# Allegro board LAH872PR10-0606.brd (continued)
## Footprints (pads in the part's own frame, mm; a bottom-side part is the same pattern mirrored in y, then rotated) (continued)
2N7002K_SOT23-3
  oval 1.016x1.524 smd: 1(0,0) 2(0.965,2.083) 3(-0.965,2.083)
2N7002KDW_SOT363-6
  oval 0.356x0.889 smd: 1(0,0) 2(0.65,0) 3(1.3,0) 4(1.3,1.6) 5(0.65,1.6) 6(0,1.6)
2N7002KW_SOT323-3
  oval 0.66x0.864 smd: 1(0,0) 2(0.65,1.85) 3(-0.65,1.85)
5A_Z80_0805_2P
  rect 0.813x1.397 smd: 1(0,0) 2(1.702,0)
5A_Z80_0805_2P-NPM
  rect 0.813x1.397 smd: 1(0,0) 2(1.702,0)
5A_Z150_1210_2P
  rect 0.991x2.997 smd: 1(0,0) 2(2.7,0)
ACES_50224-00401-001_4P
  oval 0.61x1.549 smd: 1(0,0) 2(1,0) 3(2,0) 4(3,0)
  rect 1.194x1.803 smd: 5(4.3,-3.875) 6(-1.3,-3.875)
ACES_50458-00601-001_6P-T
  oval 0.559x1.6 smd: 1(0,0) 2(2,0) 3(4,0) 4(6,0) 5(8,0) 6(10,0)
  rect 1.295x2.057 smd: 7(-3.1,-5.175) 8(13.1,-5.175)
ACES_50458-01001-P01_10P-T
  oval 0.559x1.803 smd: 1(0,0) 2(2,0) 3(4,0) 4(6,0) 5(8,0) 6(10,0) 7(12,0) 8(14,0) 9(16,0) 10(18,0)
  rect 1.295x2.057 smd: 11(-3.1,-5.275) 12(21.1,-5.275)
ACES_50673-0120N-001_12P-T
  oval 0.61x1.499 smd: 1(0,0) 3(-1,0) 5(-2,0) 7(-3,0) 9(-4,0) 11(-5,0) 13(-6,0) 15(-7,0) 17(-8,0) 19(-9,0) 21(-10,0) 23(-11,0)
  oval 0.61x1.194 smd: 2(0,2.85) 4(-1,2.85) 6(-2,2.85) 8(-3,2.85) 10(-4,2.85) 12(-5,2.85) 14(-6,2.85) 16(-7,2.85) 18(-8,2.85) 20(-9,2.85) 22(-10,2.85) 24(-11,2.85)
  rect 1.702x2.311 smd: 25(-13.25,1.425) 26(2.25,1.425)
ACES_51522-00801-001_8P
  oval 0.305x1.295 smd: 1(0,0) 2(0.5,0) 3(1,0) 4(1.5,0) 5(2,0) 6(2.5,0) 7(3,0) 8(3.5,0)
  rect 2.489x1.905 smd: 9(5.65,-3.3) 10(-2.15,-3.3)
ACES_51524-0080N-001_8P
  oval 0.61x1.295 smd: 1(0,0) 2(1,0) 3(2,0) 4(3,0) 5(4,0) 6(5,0) 7(6,0) 8(7,0)
  rect 2.489x2.21 smd: 9(10,-3.05) 10(-3,-3.05)
ACES_51524-0160N-001_16P
  oval 0.61x1.295 smd: 1(0,0) 2(1,0) 3(2,0) 4(3,0) 5(4,0) 6(5,0) 7(6,0) 8(7,0) 9(8,0) 10(9,0) 11(10,0) 12(11,0) 13(12,0) 14(13,0) 15(14,0) 16(15,0)
  rect 2.159x2.21 smd: 17(-2.825,-3.05) 18(17.825,-3.05)
ACES_51540-04001-P01_40P
  oval 0.305x1.092 smd: 1(0,0) 2(0.5,0) 3(1,0) 4(1.5,0) 5(2,0) 6(2.5,0) 7(3,0) 8(3.5,0) 9(4,0) 10(4.5,0) 11(5,0) 12(5.5,0) 13(6,0) 14(6.5,0) 15(7,0) 16(7.5,0) 17(8,0) 18(8.5,0) 19(9,0) 20(9.5,0) 21(10,0) 22(10.5,0) 23(11,0) 24(11.5,0) 25(12,0) 26(12.5,0) 27(13,0) 28(13.5,0) 29(14,0) 30(14.5,0) 31(15,0) 32(15.5,0) 33(16,0) 34(16.5,0) 35(17,0) 36(17.5,0) 37(18,0) 38(18.5,0) 39(19,0) 40(19.5,0)
  rect 0.787x2.489 smd: 41(21.2,-3.6) 42(-1.7,-3.6)
ACES_51575-00401-001_4P
  oval 0.406x0.838 smd: 1(0,0) 2(1,0) 3(2,0) 4(3,0)
  rect 0.787x2.007 smd: 5(-2.2,-3.175) 6(5.2,-3.175)
ACES_51625-01201-001_12P
  oval 0.305x1.092 smd: 1(0,0) 2(0.5,0) 3(1,0) 4(1.5,0) 5(2,0) 6(2.5,0) 7(3,0) 8(3.5,0) 9(4,0) 10(4.5,0) 11(5,0) 12(5.5,0)
  rect 0.991x2.489 smd: 13(-1.8,-3.6) 14(7.3,-3.6)
ACON_HMRF6-AK120C_19P-T
  round 0.813 hole 0.559: 1(0,0) 2(0.5,1.55) 3(1,0) 4(1.5,1.55) 5(2,0) 6(2.5,1.55) 7(3,0) 8(3.5,1.55) 9(4,0) 10(4.5,1.55) 11(5,0) 12(5.5,1.55) 13(6,0) 14(6.5,1.55) 15(7,0) 16(7.5,1.55) 17(8,0) 18(8.5,1.55) 19(9,0)
  oval 1.499x2.21 hole 0.889x1.6: 20(11.75,1.7) 21(13.65,-7.75) 22(-4.65,-6.5) 23(-2.75,1.7)
ACON_TARAN-9R1391_9P
  round 0.991 hole 0.711: 1(0,0) 2(-2.5,0) 3(-4.5,0) 4(-7,0) 5(-7.5,-1.5) 6(-5.5,-1.5) 7(-3.5,-1.5) 8(-1.5,-1.5) 9(0.5,-1.5)
  oval 1.397x3.2 hole 0.787x2.591: 10(-11.35,-2.38) 12(4.35,-2.38)
  oval 1.397x2.388 hole 0.787x1.803: 11(-11.35,-9.48) 13(4.35,-9.48)
ALC3204-CG_MQFN40_5X5
  oval 0.889x0.203 smd: 1(0,0) 2(0,-0.4) 3(0,-0.8) 4(0,-1.2) 5(0,-1.6) 6(0,-2) 7(0,-2.4) 8(0,-2.8) 9(0,-3.2) 10(0,-3.6) 21(5.1,-3.6) 22(5.1,-3.2) 23(5.1,-2.8) 24(5.1,-2.4) 25(5.1,-2) 26(5.1,-1.6) 27(5.1,-1.2) 28(5.1,-0.8) 29(5.1,-0.4) 30(5.1,0)
  oval 0.203x0.889 smd: 11(0.75,-4.35) 12(1.15,-4.35) 13(1.55,-4.35) 14(1.95,-4.35) 15(2.35,-4.35) 16(2.75,-4.35) 17(3.15,-4.35) 18(3.55,-4.35) 19(3.95,-4.35) 20(4.35,-4.35) 31(4.35,0.75) 32(3.95,0.75) 33(3.55,0.75) 34(3.15,0.75) 35(2.75,0.75) 36(2.35,0.75) 37(1.95,0.75) 38(1.55,0.75) 39(1.15,0.75) 40(0.75,0.75)
  rect 3.607x3.607 smd: 41(2.55,-1.8)
AO3416_SOT23-3
  oval 1.016x1.524 smd: 1(0,0) 2(0.965,2.083) 3(-0.965,2.083)
AO4430L_SO8
  oval 0.635x1.854 smd: 1(0,0) 2(1.27,0) 3(2.54,0) 4(3.81,0) 5(3.81,5.165) 6(2.54,5.165) 7(1.27,5.165) 8(0,5.165)
AON6380_DFN5X6-8-5
  oval 0.508x0.838 smd: 1(0,0) 2(1.27,0) 3(2.54,0) 4(3.81,0)
  custom 1.15x1.15 smd: 5(1.905,3.69)
AON7506_DFN3X3-8-5
  oval 0.406x0.991 smd: 1(0,0) 2(0.66,0) 3(1.32,0) 4(1.98,0)
  custom 0.559x0.559 smd: 5(0.99,2.247)
AON7702L_DFN8-5
  oval 0.406x0.991 smd: 1(0,0) 2(0.66,0) 3(1.32,0) 4(1.98,0)
  custom 0.559x0.559 smd: 5(0.99,2.247)
AONH36334_DFN3X3A8-10
  oval 0.457x0.813 smd: 1(0,0) 2(0.65,0) 3(1.3,0) 4(1.95,0) 5(1.95,3.18) 6(1.3,3.18) 7(0.65,3.18) 8(0,3.18)
  rect 2.388x0.991 smd: 9(0.975,2.025)
  rect 2.388x0.508 smd: 10(0.975,0.92)
AP2138N-1P5TRG1_SOT23-3
  oval 1.016x1.524 smd: 1(0,0) 2(0.965,2.083) 3(-0.965,2.083)
APL5336KAI-TRL_SOP8P8
  oval 0.635x1.854 smd: 1(0,0) 2(1.27,0) 3(2.54,0) 4(3.81,0) 5(3.81,5.165) 6(2.54,5.165) 7(1.27,5.165) 8(0,5.165)
  rect 2.87x2.489 smd: 9(1.905,2.582)
AZ5123-02SPR7G_SOT23-3
  oval 1.016x1.524 smd: 1(0,0) 2(0.965,2.083) 3(-0.965,2.083)
AZC199-02SPR7G_SOT23-3
  oval 1.016x1.524 smd: 1(0,0) 2(0.965,2.083) 3(-0.965,2.083)
AZV3002RL-7_U-FLGA8_1P65X1P65
  oval 0.406x0.508 smd: 1(0,0)
  oval 0.305x0.508 smd: 2(0.55,0) 3(1.05,0) 5(1.05,1.22) 6(0.55,1.22) 7(0.05,1.22)
  oval 0.508x0.305 smd: 4(1.15,0.61) 8(-0.05,0.61)
BAS40C_SOT23-3
  oval 1.016x1.524 smd: 1(0,0) 2(0.965,2.083) 3(-0.965,2.083)
BAT54ATB_SOT523-3
  oval 0.406x0.457 smd: 1(0,0) 2(0.5,1.35) 3(-0.5,1.35)
BAT54CW_SOT323-3
  oval 0.711x0.889 smd: 1(0,0) 2(-0.65,-1.9) 3(0.65,-1.9)
BAV99W_SC70-3
  oval 0.508x0.559 smd: 1(0,0) 2(-0.65,-1.85) 3(0.65,-1.85)
BOTH_NS0014-LF_16P
  oval 0.762x1.905 smd: 1(0,0) 2(1.27,0) 3(2.54,0) 4(3.81,0) 5(5.08,0) 6(6.35,0) 7(7.62,0) 8(8.89,0) 9(8.89,8.8) 10(7.62,8.8) 11(6.35,8.8) 12(5.08,8.8) 13(3.81,8.8) 14(2.54,8.8) 15(1.27,8.8) 16(0,8.8)
C_6P3X4P5
  oval 3.505x1.6 smd: 1(0,0) 2(5.6,0)
C_0201
  rect 0.381x0.356 smd: 1(0,0) 2(0.584,0)
C_0402
  rect 0.508x0.584 smd: 1(0,0) 2(0.914,0)
C_0603
  rect 0.635x0.889 smd: 1(0,0) 2(1.397,0)
C_0805
  rect 0.813x1.397 smd: 1(0,0) 2(1.702,0)
C_1206
  rect 1.016x1.778 smd: 1(0,0) 2(2.667,0)
C_B2
  rect 1.346x2.692 smd: 1(0,0) 2(-2.75,0)
C_D2
  rect 2.388x2.794 smd: 1(0,0) 2(6.4,0)
C_D3
  rect 2.388x2.794 smd: 1(0,0) 2(6.4,0)
CK0402101V05_0402-2
  rect 0.508x0.559 smd: 1(0,0) 2(0.92,0)
DMN65D8LDW-7_SOT363-6
  oval 0.432x0.61 smd: 1(0,0) 2(0.65,0) 3(1.3,0) 4(1.3,1.9) 5(0.65,1.9) 6(0,1.9)
DMN65D8LW-7_SOT323-3
  oval 0.711x0.889 smd: 1(0,0) 2(-0.65,-1.9) 3(0.65,-1.9)
DMN66D0LDW-7_SOT363-6
  oval 0.432x0.61 smd: 1(0,0) 2(0.65,0) 3(1.3,0) 4(1.3,1.9) 5(0.65,1.9) 6(0,1.9)
EMB04N03H_EDFN5X6-8-5
  oval 0.61x1.27 smd: 1(0,0) 2(1.27,0) 3(2.54,0) 4(3.81,0)
  custom 1.105x1.105 smd: 5(1.905,3.715)
F_1206L150PR
  rect 0.991x1.803 smd: 1(0,0) 2(2.8,0)
F_MF-NSMF050-2
  rect 0.991x1.6 smd: 1(0,0) 2(3,0)
F_SMD1812P110TF-24
  rect 1.778x3.15 smd: 1(0,0) 2(5.23,0)
F_T0603FF1000TM
  rect 0.711x0.991 smd: 1(0,0) 2(1.5,0)
FDV301N-G_SOT23-3
  oval 1.016x1.524 smd: 1(0,0) 2(0.965,2.083) 3(-0.965,2.083)
FIDUCIAL_C40M80
  round 1.016 smd: 1(0,0)
G2042RD1U_TDFN8_3X3
  oval 0.457x0.94 smd: 1(0,0) 2(0.65,0) 3(1.3,0) 4(1.95,0) 5(1.95,3.05) 6(1.3,3.05) 7(0.65,3.05) 8(0,3.05)
  rect 2.311x1.499 smd: 9(0.975,1.525)
H_3P0-G
  round 3.505 hole 2.997: 1(0,0)
H_3P0X4P0
  oval 3.505x4.496 hole 2.997x3.988: 1(0,0)
H_3P2
  round 3.708 hole 3.2: 1(0,0)
H_3P3-G
  round 3.81 hole 3.302: 1(0,0)
H_3P9
  round 4.42 hole 3.912: 1(0,0)
H_5P6N
  round 5.588 hole 5.588 unplated: (0,0)
HEFEN_AFB02-S30F1A-HF_30P-T
  oval 0.229x1.092 smd: 1(0,0) 2(-0.8,0) 3(-1.6,0) 4(-2.4,0) 5(-3.2,0) 6(-4,0) 7(-4.8,0) 8(-5.6,0) 9(-6.4,0) 10(-7.2,0) 11(-8,0) 12(-8.8,0) 13(-9.6,0) 14(-10.4,0) 15(-11.2,0) 16(-12,0) 17(-12.8,0) 18(-13.6,0) 19(-14.4,0) 20(-15.2,0) 21(-16,0) 22(-16.8,0) 23(-17.6,0) 24(-18.4,0) 25(-19.2,0) 26(-20,0) 27(-20.8,0) 28(-21.6,0) 29(-22.4,0) 30(-23.2,0)
  rect 0.559x1.295 smd: 31(1.475,-3.45) 32(-24.675,-3.45)
INPAQ_HCM1012GH900BP_4P
  rect 0.711x0.305 smd: 1(0,0) 2(1.25,0) 3(1.25,-0.5) 4(0,-0.5)
INPAQ_HCM1012GH900BP_4P-NPM
  rect 0.711x0.305 smd: 1(0,0) 2(1.25,0) 3(1.25,-0.5) 4(0,-0.5)
INPAQ_MCM1012B900F06BP_4P
  rect 0.711x0.305 smd: 1(0,0) 2(1.25,0) 3(1.25,-0.5) 4(0,-0.5)
ISL62771HRTZ-T_TQFN40_5X5-S
  oval 0.203x1.016 smd: 1(0,0) 2(0.4,0) 3(0.8,0) 4(1.2,0) 5(1.6,0) 6(2,0) 7(2.4,0) 8(2.8,0) 9(3.2,0) 10(3.6,0) 21(3.6,4.975) 22(3.2,4.975) 23(2.8,4.975) 24(2.4,4.975) 25(2,4.975) 26(1.6,4.975) 27(1.2,4.975) 28(0.8,4.975) 29(0.4,4.975) 30(0,4.975)
  oval 1.016x0.203 smd: 11(4.288,0.688) 12(4.288,1.088) 13(4.288,1.488) 14(4.288,1.888) 15(4.288,2.288) 16(4.288,2.688) 17(4.288,3.088) 18(4.288,3.488) 19(4.288,3.888) 20(4.288,4.288) 31(-0.688,4.288) 32(-0.688,3.888) 33(-0.688,3.488) 34(-0.688,3.088) 35(-0.688,2.688) 36(-0.688,2.288) 37(-0.688,1.888) 38(-0.688,1.488) 39(-0.688,1.088) 40(-0.688,0.688)
  rect 3.505x3.505 smd: 41(1.8,2.488)
ISL95522HRZ-T_TQFN32_4X4
  oval 0.94x0.254 smd: 1(0,0) 2(0,-0.4) 3(0,-0.8) 4(0,-1.2) 5(0,-1.6) 6(0,-2) 7(0,-2.4) 8(0,-2.8) 17(4.1,-2.8) 18(4.1,-2.4) 19(4.1,-2) 20(4.1,-1.6) 21(4.1,-1.2) 22(4.1,-0.8) 23(4.1,-0.4) 24(4.1,0)
  oval 0.254x0.94 smd: 9(0.65,-3.45) 10(1.05,-3.45) 11(1.45,-3.45) 12(1.85,-3.45) 13(2.25,-3.45) 14(2.65,-3.45) 15(3.05,-3.45) 16(3.45,-3.45) 25(3.45,0.65) 26(3.05,0.65) 27(2.65,0.65) 28(2.25,0.65) 29(1.85,0.65) 30(1.45,0.65) 31(1.05,0.65) 32(0.65,0.65)
  rect 2.642x2.642 smd: 33(2.05,-1.4)
JUMP_43X39
  custom 0.191x0.191 smd: 1(0,0) 2(0.914,0)
JUMP_43X39-NPM
  custom 0.191x0.191 smd: 1(0,0) 2(0.914,0)
JUMP_43X79
  custom 0.188x0.188 smd: 1(0,0) 2(1.1,0)
JUMP_43X79-NPM
  custom 0.188x0.188 smd: 1(0,0) 2(1.1,0)
JUMP_43X118
  custom 0.187x0.187 smd: 1(0,0) 2(1.1,0)
JUMP_43X118-NPM
  custom 0.187x0.187 smd: 1(0,0) 2(1.1,0)
JXT_FP226H-004S1AM_4P
  oval 0.61x1.295 smd: 1(0,0) 2(1,0) 3(2,0) 4(3,0)
  rect 0.991x2.007 smd: 5(-2.6,-3.25) 6(5.6,-3.25)
KB9542Q-B_LQFP128_14X14
  oval 1.803x0.254 smd: 1(0,0) 2(0,-0.4) 3(0,-0.8) 4(0,-1.2) 5(0,-1.6) 6(0,-2) 7(0,-2.4) 8(0,-2.8) 9(0,-3.2) 10(0,-3.6) 11(0,-4) 12(0,-4.4) 13(0,-4.8) 14(0,-5.2) 15(0,-5.6) 16(0,-6) 17(0,-6.4) 18(0,-6.8) 19(0,-7.2) 20(0,-7.6) 21(0,-8) 22(0,-8.4) 23(0,-8.8) 24(0,-9.2) 25(0,-9.6) 26(0,-10) 27(0,-10.4) 28(0,-10.8) 29(0,-11.2) 30(0,-11.6) 31(0,-12) 32(0,-12.4) 65(15.654,-12.4) 66(15.654,-12) 67(15.654,-11.6) 68(15.654,-11.2) 69(15.654,-10.8) 70(15.654,-10.4) 71(15.654,-10) 72(15.654,-9.6) 73(15.654,-9.2) 74(15.654,-8.8) 75(15.654,-8.4) 76(15.654,-8) 77(15.654,-7.6) 78(15.654,-7.2) 79(15.654,-6.8) 80(15.654,-6.4) 81(15.654,-6) 82(15.654,-5.6) 83(15.654,-5.2) 84(15.654,-4.8) 85(15.654,-4.4) 86(15.654,-4) 87(15.654,-3.6) 88(15.654,-3.2) 89(15.654,-2.8) 90(15.654,-2.4) 91(15.654,-2) 92(15.654,-1.6) 93(15.654,-1.2) 94(15.654,-0.8) 95(15.654,-0.4) 96(15.654,0)
  oval 0.254x1.803 smd: 33(1.627,-14.027) 34(2.027,-14.027) 35(2.427,-14.027) 36(2.827,-14.027) 37(3.227,-14.027) 38(3.627,-14.027) 39(4.027,-14.027) 40(4.427,-14.027) 41(4.827,-14.027) 42(5.227,-14.027) 43(5.627,-14.027) 44(6.027,-14.027) 45(6.427,-14.027) 46(6.827,-14.027) 47(7.227,-14.027) 48(7.627,-14.027) 49(8.027,-14.027) 50(8.427,-14.027) 51(8.827,-14.027) 52(9.227,-14.027) 53(9.627,-14.027) 54(10.027,-14.027) 55(10.427,-14.027) 56(10.827,-14.027) 57(11.227,-14.027) 58(11.627,-14.027) 59(12.027,-14.027) 60(12.427,-14.027) 61(12.827,-14.027) 62(13.227,-14.027) 63(13.627,-14.027) 64(14.027,-14.027) 97(14.027,1.627) 98(13.627,1.627) 99(13.227,1.627) 100(12.827,1.627) 101(12.427,1.627) 102(12.027,1.627) 103(11.627,1.627) 104(11.227,1.627) 105(10.827,1.627) 106(10.427,1.627) 107(10.027,1.627) 108(9.627,1.627) 109(9.227,1.627) 110(8.827,1.627) 111(8.427,1.627) 112(8.027,1.627) 113(7.627,1.627) 114(7.227,1.627) 115(6.827,1.627) 116(6.427,1.627) 117(6.027,1.627) 118(5.627,1.627) 119(5.227,1.627) 120(4.827,1.627) 121(4.427,1.627) 122(4.027,1.627) 123(3.627,1.627) 124(3.227,1.627) 125(2.827,1.627) 126(2.427,1.627) 127(2.027,1.627) 128(1.627,1.627)
KC_FBMA-L11-201209-121LMA50_2P
  rect 0.991x1.702 smd: 1(0,0) 2(1.5,0)
L2N7002DW1T1G_SC88-6
  oval 0.406x0.508 smd: 1(0,0) 2(0.65,0) 3(1.3,0) 4(1.3,1.9) 5(0.65,1.9) 6(0,1.9)
L03ESDL5V0CC3-2_SOT23-3
  oval 1.016x1.524 smd: 1(0,0) 2(0.965,2.083) 3(-0.965,2.083)
L03ESDL5V0CG3-2_SOT-523-3
  oval 0.406x0.787 smd: 1(0,0) 2(-0.5,-1.4) 3(0.5,-1.4)
L05ESDL5V0NA-4_SLP2510P8-10-9
  rect 0.203x0.686 smd: 1(0,0) 2(-0.5,0) 4(-1.5,0) 5(-2,0) 6(-2,-0.875) 7(-1.5,-0.875) 8(-0.5,-0.875) 9(0,-0.875)
  rect 0.406x1.549 smd: 3(-1,-0.437)
L_5X5X3_M_2P
  rect 2.159x2.794 smd: 1(0,0) 2(4.35,0)
L_7X7X3_M_2P
  rect 2.362x3.505 smd: 1(0,0) 2(6.05,0)
L_7X7X4_M_4P
  custom 0.686x0.686 smd: 1(0,0) 4(8.357,0)
  rect 2.21x0.508 smd: 2(1.448,0) 3(6.909,0)
LCN_DAN05-67306-0103_75P
  round 1.092 hole 1.092 unplated: (-0.75,-5.275)
  round 1.6 hole 1.6 unplated: (19.25,-5.275)
  oval 0.305x1.549 smd: 1(0,0) 2(0.25,-7.55) 3(0.5,0) 4(0.75,-7.55) 5(1,0) 6(1.25,-7.55) 7(1.5,0) 8(1.75,-7.55) 9(2,0) 10(2.25,-7.55) 11(2.5,0) 12(2.75,-7.55) 13(3,0) 14(3.25,-7.55) 15(3.5,0) 16(3.75,-7.55) 17(4,0) 18(4.25,-7.55) 19(4.5,0) 20(4.75,-7.55) 21(5,0) 22(5.25,-7.55) 23(5.5,0) 24(5.75,-7.55) 25(6,0) 26(6.25,-7.55) 27(6.5,0) 28(6.75,-7.55) 29(7,0) 30(7.25,-7.55) 31(7.5,0) 32(7.75,-7.55) 33(8,0) 34(8.25,-7.55) 35(8.5,0) 36(8.75,-7.55) 37(9,0) 38(9.25,-7.55) 39(9.5,0) 40(9.75,-7.55) 41(10,0) 42(10.25,-7.55) 43(10.5,0) 44(10.75,-7.55) 45(11,0) 46(11.25,-7.55) 47(11.5,0) 48(11.75,-7.55) 49(12,0) 50(12.25,-7.55) 51(12.5,0) 52(12.75,-7.55) 53(13,0) 54(13.25,-7.55) 55(13.5,0) 56(13.75,-7.55) 57(14,0) 58(14.25,-7.55) 67(16.5,0) 68(16.75,-7.55) 69(17,0) 70(17.25,-7.55) 71(17.5,0) 72(17.75,-7.55) 73(18,0) 74(18.25,-7.55) 75(18.5,0)
  rect 1.194x2.743 smd: 76(19.6,-0.775) 77(-1.1,-0.775)
LED_LTW-295DSKS-5A_4P
  rect 0.508x0.406 smd: 1(0,0) 2(1.2,0) 3(0,0.7) 4(1.2,0.7)
LM393DR_SO8
  oval 0.635x1.854 smd: 1(0,0) 2(1.27,0) 3(2.54,0) 4(3.81,0) 5(3.81,5.165) 6(2.54,5.165) 7(1.27,5.165) 8(0,5.165)
LMBT3904LT1G_SOT23-3
  oval 1.016x1.524 smd: 1(0,0) 2(0.965,2.083) 3(-0.965,2.083)
LMUN5113T1G_SOT323-3
  oval 0.711x0.889 smd: 1(0,0) 2(0.65,1.9) 3(-0.65,1.9)
LN2306LT1G_SOT23-3
  oval 1.016x1.524 smd: 1(0,0) 2(0.965,2.083) 3(-0.965,2.083)
LNG2DMTR_LGA12_2X2
  oval 0.406x0.305 smd: 1(0,0) 4(0,-1.5) 7(1.602,-1.5) 10(1.602,0)
  oval 0.508x0.305 smd: 2(0.051,-0.5) 3(0.051,-1) 8(1.551,-1) 9(1.551,-0.5)
  oval 0.305x0.508 smd: 5(0.551,-1.5) 6(1.051,-1.5) 11(1.051,0) 12(0.551,0)
LOTES_AAA-BAT-054-K01_2P
  round 0.787 hole 0.787 unplated: (-14.5,-8)
  round 1.194 hole 1.194 unplated: (-14.5,8)
  rect 2.007x3.988 smd: 1(0,0) 2(-30.1,0)
LOTES_ADDR0206-P001A02_260P
  round 1.092 hole 1.092 unplated: (-67.775,-4.1)
  round 1.6 hole 1.6 unplated: (1.025,-4.1)
  oval 0.305x1.753 smd: 1(0,0) 2(-0.25,-8.2) 3(-0.5,0) 4(-0.75,-8.2) 5(-1,0) 6(-1.25,-8.2) 7(-1.5,0) 8(-1.75,-8.2) 9(-2,0) 10(-2.25,-8.2) 11(-2.5,0) 12(-2.75,-8.2) 13(-3,0) 14(-3.25,-8.2) 15(-3.5,0) 16(-3.75,-8.2) 17(-4,0) 18(-4.25,-8.2) 19(-4.5,0) 20(-4.75,-8.2) 21(-5,0) 22(-5.25,-8.2) 23(-5.5,0) 24(-5.75,-8.2) 25(-6,0) 26(-6.25,-8.2) 27(-6.5,0) 28(-6.75,-8.2) 29(-7,0) 30(-7.25,-8.2) 31(-7.5,0) 32(-7.75,-8.2) 33(-8,0) 34(-8.25,-8.2) 35(-8.5,0) 36(-8.75,-8.2) 37(-9,0) 38(-9.25,-8.2) 39(-9.5,0) 40(-9.75,-8.2) 41(-10,0) 42(-10.25,-8.2) 43(-10.5,0) 44(-10.75,-8.2) 45(-11,0) 46(-11.25,-8.2) 47(-11.5,0) 48(-11.75,-8.2) 49(-12,0) 50(-12.25,-8.2) 51(-12.5,0) 52(-12.75,-8.2) 53(-13,0) 54(-13.25,-8.2) 55(-13.5,0) 56(-13.75,-8.2) 57(-14,0) 58(-14.25,-8.2) 59(-14.5,0) 60(-14.75,-8.2) 61(-15,0) 62(-15.25,-8.2) 63(-15.5,0) 64(-15.75,-8.2) 65(-16,0) 66(-16.25,-8.2) 67(-16.5,0) 68(-16.75,-8.2) 69(-17,0) 70(-17.25,-8.2) 71(-17.5,0) 72(-17.75,-8.2) 73(-18,0) 74(-18.25,-8.2) 75(-18.5,0) 76(-18.75,-8.2) 77(-19,0) 78(-19.25,-8.2) 79(-19.5,0) 80(-19.75,-8.2) 81(-20,0) 82(-20.25,-8.2) 83(-20.5,0) 84(-20.75,-8.2) 85(-21,0) 86(-21.25,-8.2) 87(-21.5,0) 88(-21.75,-8.2) 89(-22,0) 90(-22.25,-8.2) 91(-22.5,0) 92(-22.75,-8.2) 93(-23,0) 94(-23.25,-8.2) 95(-23.5,0) 96(-23.75,-8.2) 97(-24,0) 98(-24.25,-8.2) 99(-24.5,0) 100(-24.75,-8.2) 101(-25,0) 102(-25.25,-8.2) 103(-25.5,0) 104(-25.75,-8.2) 105(-26,0) 106(-26.25,-8.2) 107(-26.5,0) 108(-26.75,-8.2) 109(-27,0) 110(-27.25,-8.2) 111(-27.5,0) 112(-27.75,-8.2) 113(-28,0) 114(-28.25,-8.2) 115(-28.5,0) 116(-28.75,-8.2) 117(-29,0) 118(-29.25,-8.2) 119(-29.5,0) 120(-29.75,-8.2) 121(-30,0) 122(-30.25,-8.2) 123(-30.5,0) 124(-30.75,-8.2) 125(-31,0) 126(-31.25,-8.2) 127(-31.5,0) 128(-31.75,-8.2) 129(-32,0) 130(-32.25,-8.2) 131(-32.5,0) 132(-32.75,-8.2) 133(-33,0) 134(-33.25,-8.2) 135(-33.5,0) 136(-33.75,-8.2) 137(-34,0) 138(-34.25,-8.2) 139(-34.5,0) 140(-34.75,-8.2) 141(-35,0) 142(-35.25,-8.2) 143(-35.5,0) 144(-35.75,-8.2) 145(-38,0) 146(-38.25,-8.2) 147(-38.5,0) 148(-38.75,-8.2) 149(-39,0) 150(-39.25,-8.2) 151(-39.5,0) 152(-39.75,-8.2) 153(-40,0) 154(-40.25,-8.2) 155(-40.5,0) 156(-40.75,-8.2) 157(-41,0) 158(-41.25,-8.2) 159(-41.5,0) 160(-41.75,-8.2) 161(-42,0) 162(-42.25,-8.2) 163(-42.5,0) 164(-42.75,-8.2) 165(-43,0) 166(-43.25,-8.2) 167(-43.5,0) 168(-43.75,-8.2) 169(-44,0) 170(-44.25,-8.2) 171(-44.5,0) 172(-44.75,-8.2) 173(-45,0) 174(-45.25,-8.2) 175(-45.5,0) 176(-45.75,-8.2) 177(-46,0) 178(-46.25,-8.2) 179(-46.5,0) 180(-46.75,-8.2) 181(-47,0) 182(-47.25,-8.2) 183(-47.5,0) 184(-47.75,-8.2) 185(-48,0) 186(-48.25,-8.2) 187(-48.5,0) 188(-48.75,-8.2) 189(-49,0) 190(-49.25,-8.2) 191(-49.5,0) 192(-49.75,-8.2) 193(-50,0) 194(-50.25,-8.2) 195(-50.5,0) 196(-50.75,-8.2) 197(-51,0) 198(-51.25,-8.2) 199(-51.5,0) 200(-51.75,-8.2) 201(-52,0) 202(-52.25,-8.2) 203(-52.5,0) 204(-52.75,-8.2) 205(-53,0) 206(-53.25,-8.2) 207(-53.5,0) 208(-53.75,-8.2) 209(-54,0) 210(-54.25,-8.2) 211(-54.5,0) 212(-54.75,-8.2) 213(-55,0) 214(-55.25,-8.2) 215(-55.5,0) 216(-55.75,-8.2) 217(-56,0) 218(-56.25,-8.2) 219(-56.5,0) 220(-56.75,-8.2) 221(-57,0) 222(-57.25,-8.2) 223(-57.5,0) 224(-57.75,-8.2) 225(-58,0) 226(-58.25,-8.2) 227(-58.5,0) 228(-58.75,-8.2) 229(-59,0) 230(-59.25,-8.2) 231(-59.5,0) 232(-59.75,-8.2) 233(-60,0) 234(-60.25,-8.2) 235(-60.5,0) 236(-60.75,-8.2) 237(-61,0) 238(-61.25,-8.2) 239(-61.5,0) 240(-61.75,-8.2) 241(-62,0) 242(-62.25,-8.2) 243(-62.5,0) 244(-62.75,-8.2) 245(-63,0) 246(-63.25,-8.2) 247(-63.5,0) 248(-63.75,-8.2) 249(-64,0) 250(-64.25,-8.2) 251(-64.5,0) 252(-64.75,-8.2) 253(-65,0) 254(-65.25,-8.2) 255(-65.5,0) 256(-65.75,-8.2) 257(-66,0) 258(-66.25,-8.2) 259(-66.5,0) 260(-66.75,-8.2)
  rect 3.505x4.597 smd: 261(-67.175,7.9) 262(0.425,7.9)
LOTES_APCI0136-P001A_75P
  round 1.092 hole 1.092 unplated: (-0.75,-5.275)
  round 1.6 hole 1.6 unplated: (19.25,-5.275)
  oval 0.305x1.549 smd: 1(0,0) 2(0.25,-7.55) 3(0.5,0) 4(0.75,-7.55) 5(1,0) 6(1.25,-7.55) 7(1.5,0) 8(1.75,-7.55) 9(2,0) 10(2.25,-7.55) 11(2.5,0) 12(2.75,-7.55) 13(3,0) 14(3.25,-7.55) 15(3.5,0) 16(3.75,-7.55) 17(4,0) 18(4.25,-7.55) 19(4.5,0) 20(4.75,-7.55) 21(5,0) 22(5.25,-7.55) 23(5.5,0) 32(7.75,-7.55) 33(8,0) 34(8.25,-7.55) 35(8.5,0) 36(8.75,-7.55) 37(9,0) 38(9.25,-7.55) 39(9.5,0) 40(9.75,-7.55) 41(10,0) 42(10.25,-7.55) 43(10.5,0) 44(10.75,-7.55) 45(11,0) 46(11.25,-7.55) 47(11.5,0) 48(11.75,-7.55) 49(12,0) 50(12.25,-7.55) 51(12.5,0) 52(12.75,-7.55) 53(13,0) 54(13.25,-7.55) 55(13.5,0) 56(13.75,-7.55) 57(14,0) 58(14.25,-7.55) 59(14.5,0) 60(14.75,-7.55) 61(15,0) 62(15.25,-7.55) 63(15.5,0) 64(15.75,-7.55) 65(16,0) 66(16.25,-7.55) 67(16.5,0) 68(16.75,-7.55) 69(17,0) 70(17.25,-7.55) 71(17.5,0) 72(17.75,-7.55) 73(18,0) 74(18.25,-7.55) 75(18.5,0)
  rect 1.194x2.743 smd: 76(-1.1,-0.775) 77(19.6,-0.775)
LRB715FT1G_SOT323-3
  oval 0.711x0.889 smd: 1(0,0) 2(0.65,1.9) 3(-0.65,1.9)
LTC015EUBFS8TL_UMT3F
  oval 0.787x0.889 smd: 1(0,0) 2(-0.65,-1.6) 3(0.65,-1.6)
MESS138W-G_SOT323-3
  oval 0.711x0.889 smd: 1(0,0) 2(-0.65,-1.9) 3(0.65,-1.9)
MMBT3904_NL_SOT23-3
  oval 1.016x1.524 smd: 1(0,0) 2(0.965,2.083) 3(-0.965,2.083)
MMST3904-7-F_SOT323-3
  oval 0.711x0.889 smd: 1(0,0) 2(0.65,1.9) 3(-0.65,1.9)
MURAT_BLM15AG102SN1D_2P
  rect 0.457x0.508 smd: 1(0,0) 2(0.85,0)
MURAT_BLM15BD121SN1D_2P
  rect 0.457x0.508 smd: 1(0,0) 2(0.85,0)
MURAT_BLM15PX221SN1D_2P
  rect 0.457x0.508 smd: 1(0,0) 2(0.85,0)
MURAT_BLM15PX330SN1D_2P
  rect 0.457x0.508 smd: 1(0,0) 2(0.85,0)
NC7SZ08P5X_NL_SC70-5
  oval 0.457x0.711 smd: 1(-0.65,-0.925) 2(0,-0.925) 3(0.65,-0.925) 4(0.65,0.925) 5(-0.65,0.925)
NCT7718W_MSOP8
  oval 0.381x1.575 smd: 1(0,0) 2(0.65,0) 3(1.3,0) 4(1.95,0) 5(1.95,4.35) 6(1.3,4.35) 7(0.65,4.35) 8(0,4.35)
PJSOT24C_SOT23-3
  oval 1.016x1.524 smd: 1(0,0) 2(0.965,2.083) 3(-0.965,2.083)
PS8527CTQFN20GTR2A2_TQFN20_4X4
  oval 1.041x0.254 smd: 1(0,0) 2(0,-0.5) 3(0,-1) 4(0,-1.5) 5(0,-2) 11(3.95,-2) 12(3.95,-1.5) 13(3.95,-1) 14(3.95,-0.5) 15(3.95,0)
  oval 0.254x1.041 smd: 6(0.975,-2.975) 7(1.475,-2.975) 8(1.975,-2.975) 9(2.475,-2.975) 10(2.975,-2.975) 16(2.975,0.975) 17(2.475,0.975) 18(1.975,0.975) 19(1.475,0.975) 20(0.975,0.975)
  rect 2.108x2.108 smd: 21(1.975,-1)
Q_N_DFN56-8-5
  oval 0.61x1.27 smd: 1(0,0) 2(1.27,0) 3(2.54,0) 4(3.81,0)
  custom 1.105x1.105 smd: 5(1.905,3.715)
R0402_0OHM
  custom 0.14x0.14 smd: 1(0,0)
  rect 0.508x0.559 smd: 2(0.914,0)
R0603_0OHM
  custom 0.222x0.222 smd: 1(0,0)
  rect 0.635x0.889 smd: 2(1.397,0)
R0805_0OHM
  custom 0.349x0.349 smd: 1(0,0)
  rect 0.813x1.397 smd: 2(1.702,0)
R_0201
  rect 0.381x0.356 smd: 1(0,0) 2(0.584,0)
R_0402
  rect 0.508x0.559 smd: 1(0,0) 2(0.914,0)
R_0402-NPM
  rect 0.508x0.559 smd: 1(0,0) 2(0.914,0)
R_0603
  rect 0.635x0.889 smd: 1(0,0) 2(1.397,0)
R_0805
  rect 0.813x1.397 smd: 1(0,0) 2(1.702,0)
R_1206
  rect 1.016x1.651 smd: 1(0,0) 2(2.667,0)
R_1206_4P-D
  custom 0.371x0.371 smd: 1(0,0) 4(3.327,0)
  custom 0.114x0.114 smd: 2(0.775,0) 3(2.553,0)
RB520SM-30T2R_EMD2-2
  rect 0.61x0.787 smd: 1(0,0) 2(1.7,0)
RB751V-40_SOD323-2
  rect 0.787x0.889 smd: 1(0,0) 2(2.14,0)
RP_0804_8P4R
  oval 0.66x0.254 smd: 1(0,0) 2(0,-0.5) 3(0,-1) 4(0,-1.5) 5(1.15,-1.5) 6(1.15,-1) 7(1.15,-0.5) 8(1.15,0)
RT6226AGQUF_UQFN12_3X3
  oval 0.838x0.254 smd: 1(0,0) 6(3.15,0)
  oval 1.397x0.254 smd: 2(0.275,-0.72) 3(0.275,-1.62)
  oval 2.337x0.254 smd: 4(2.41,-1.17) 5(2.41,-0.45)
  oval 0.254x0.838 smd: 7(2.7,0.955) 8(2.25,0.955) 9(1.8,0.955) 10(1.35,0.955) 11(0.9,0.955) 12(0.45,0.955)
RT8061AZQW_WDFN10_3X3
  oval 0.254x0.889 smd: 1(0,0) 2(0.5,0) 3(1,0) 4(1.5,0) 5(2,0) 6(2,3.1) 7(1.5,3.1) 8(1,3.1) 9(0.5,3.1) 10(0,3.1)
  rect 2.464x1.626 smd: 11(1,1.55)
RT8207PGQW_WQFN20_3X3
  oval 0.203x0.889 smd: 1(0,0) 2(0.4,0) 3(0.8,0) 4(1.2,0) 5(1.6,0) 11(1.6,3.1) 12(1.2,3.1) 13(0.8,3.1) 14(0.4,3.1) 15(0,3.1)
  oval 0.889x0.203 smd: 6(2.35,0.75) 7(2.35,1.15) 8(2.35,1.55) 9(2.35,1.95) 10(2.35,2.35) 16(-0.75,2.35) 17(-0.75,1.95) 18(-0.75,1.55) 19(-0.75,1.15) 20(-0.75,0.75)
  rect 1.702x1.702 smd: 21(0.8,1.55)
RT9059GSP_SO8
  oval 0.635x1.854 smd: 1(0,0) 2(1.27,0) 3(2.54,0) 4(3.81,0) 5(3.81,5.157) 6(2.54,5.157) 7(1.27,5.157) 8(0,5.157)
  rect 2.311x2.311 smd: 9(1.905,2.579)
RTL8106E-CG_QFN32_4X4-S
  oval 0.203x0.838 smd: 1(0,0) 2(0.4,0) 3(0.8,0) 4(1.2,0) 5(1.6,0) 6(2,0) 7(2.4,0) 8(2.8,0) 17(2.8,4.15) 18(2.4,4.15) 19(2,4.15) 20(1.6,4.15) 21(1.2,4.15) 22(0.8,4.15) 23(0.4,4.15) 24(0,4.15)
  oval 0.838x0.203 smd: 9(3.475,0.675) 10(3.475,1.075) 11(3.475,1.475) 12(3.475,1.875) 13(3.475,2.275) 14(3.475,2.675) 15(3.475,3.075) 16(3.475,3.475) 25(-0.675,3.475) 26(-0.675,3.075) 27(-0.675,2.675) 28(-0.675,2.275) 29(-0.675,1.875) 30(-0.675,1.475) 31(-0.675,1.075) 32(-0.675,0.675)
  rect 2.692x2.692 smd: 33(1.4,2.075)
RUM002N02GT2L_VMT3
  oval 0.508x0.457 smd: 1(0,0)
  oval 0.406x0.457 smd: 2(-0.4,-1.15) 3(0.4,-1.15)
SAMTE_ASP-136446-07-B_20P-T
  oval 0.737x2.794 smd: 1(0,0) 2(0,4.07) 3(1.27,0) 4(1.27,4.07) 5(2.54,0) 6(2.54,4.07) 7(3.81,0) 8(3.81,4.07) 9(5.08,0) 10(5.08,4.07) 11(6.35,0) 12(6.35,4.07) 13(7.62,0) 14(7.62,4.07) 15(8.89,0) 16(8.89,4.07) 17(10.16,0) 18(10.16,4.07) 19(11.43,0) 20(11.43,4.07)
SHORTPADS
  custom 0.19x0.19 smd: 1(-0.483,0) 2(0.483,0)
SINGA_2RJ3076-078211F_8P-T
  round 1.295 hole 0.889: 1(0,0) 2(-1.02,1.1) 3(-2.04,0) 4(-3.06,1.1) 5(-4.08,0) 6(-5.1,1.1) 7(-6.12,0) 8(-7.14,1.1)
  oval 0.991x2.007 hole 0.61x1.6: 9(4.83,-2.3) 10(4.83,-10.1) 11(-11.97,-10.1) 12(-11.97,-2.3)
SN74LVC1G07DCKR_SC70-5
  oval 0.381x0.864 smd: 1(0,0) 2(0.65,0) 3(1.3,0) 4(1.3,1.74) 5(0,1.74)
SW_TST71-N-220-T170-S017_2P
  rect 0.61x1.499 smd: 1(0,0) 2(3.2,0)
SY6288C20AAC_SOT23-5
  oval 0.559x0.787 smd: 1(0,0) 2(0.95,0) 3(1.9,0) 4(1.9,2.4) 5(0,2.4)
SY6288D20AAC_SOT23-5
  oval 0.559x0.787 smd: 1(0,0) 2(0.95,0) 3(1.9,0) 4(1.9,2.4) 5(0,2.4)
SY8286BRAC_QFN20_3X3
  oval 0.889x0.254 smd: 1(0,0) 2(0,-0.45) 3(0,-0.9) 4(0,-1.35) 5(0,-1.8) 11(3.1,-1.8) 12(3.1,-1.35) 13(3.1,-0.9) 14(3.1,-0.45) 15(3.1,0)
  oval 0.254x0.889 smd: 6(0.65,-2.45) 7(1.1,-2.45) 8(1.55,-2.45) 9(2,-2.45) 10(2.45,-2.45) 16(2.45,0.65) 17(2,0.65) 18(1.55,0.65) 19(1.1,0.65) 20(0.65,0.65)
  rect 0.991x0.991 smd: 21(1.55,-0.9)
SY8288CRAC_QFN20_3X3
  oval 0.889x0.254 smd: 1(0,0) 2(0,-0.45) 3(0,-0.9) 4(0,-1.35) 5(0,-1.8) 11(3.1,-1.8) 12(3.1,-1.35) 13(3.1,-0.9) 14(3.1,-0.45) 15(3.1,0)
  oval 0.254x0.889 smd: 6(0.65,-2.45) 7(1.1,-2.45) 8(1.55,-2.45) 9(2,-2.45) 10(2.45,-2.45) 16(2.45,0.65) 17(2,0.65) 18(1.55,0.65) 19(1.1,0.65) 20(0.65,0.65)
  rect 0.991x0.991 smd: 21(1.55,-0.9)
TAI-T_HCB2012KF-221T30_2P
  rect 0.991x0.991 smd: 1(0,0) 2(2,0)
TPC12
  round 0.305 smd: 1(0,0)
TPS22966DPUR_SON14_2X3-S
  oval 0.254x0.813 smd: 1(0,0) 2(0.4,0) 6(2,0) 7(2.4,0) 8(2.4,2.05) 9(2,2.05) 13(0.4,2.05) 14(0,2.05)
  oval 0.203x0.762 smd: 3(0.8,0) 4(1.2,0) 5(1.6,0) 10(1.6,2.05) 11(1.2,2.05) 12(0.8,2.05)
  rect 2.489x0.889 smd: 15(1.2,1.025)
TVNST52302AB0_SOT523-3
  oval 0.508x0.559 smd: 1(0,0) 2(-0.5,-1.4) 3(0.5,-1.4)
W25Q128FWSIQ_SO8
  oval 0.635x1.676 smd: 1(0,0) 2(1.27,0) 3(2.54,0) 4(3.81,0) 5(3.81,7.25) 6(2.54,7.25) 7(1.27,7.25) 8(0,7.25)
X_7XZ3200003_4P
  rect 1.397x1.194 smd: 1(0,0) 2(2.2,0) 3(2.2,1.7) 4(0,1.7)
Y_7V25000014_4P
  rect 1.397x1.194 smd: 1(0,0) 2(2.2,0) 3(2.2,1.7) 4(0,1.7)
Y_CM31532768DZFT_2P
  rect 1.092x1.905 smd: 1(0,0) 2(2.5,0)
Y_X3S048000D81H-W_4P
  rect 1.397x1.194 smd: 1(0,0) 2(2.2,0) 3(2.2,1.7) 4(0,1.7)
YUQIU_PJ753-F07J1BE-B_7P-T
  oval 0.991x1.803 hole 0.61x1.397: 1(0,0) 2(9.5,-5.5) 3(9.5,-8.6) 4(0,-7.8) 5(9.5,0) 6(9.5,-2.75) 7(0,-2.65)

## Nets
0.95VS_GATE: C35.1 Q17.1 R58.2 U4.4
0.95VS_PWR_EN#: Q16.2 Q17.2 RE24.1 UE1.99
0.775VALW_GATE: Q20.2 Q21.2 R59.1 U5.7
1.8VS_GATE: C21.2 R52.2 U3.3
3VS_GATE: C25.2 R53.2 U2.5
3VS_LS: J4.2 U2.8 U2.9
5VS: J1.2 J2.2 U2.13 U2.14
5VS_GATE: C16.2 R51.2 U2.3
+0.6V_DDR_VTT: CD16.1 CD17.1 CD18.1 CD26.1 CD27.1 CD34.1 CD35.1 CD44.1 DD2.2 JDIMM1.258 PJPM03.2
+0.6VSP: PCM20.1 PJPM03.1 PUM01.2 PUM01.20
+0.95VALW: C28.1 C49.1 CC102.1 CC103.1 PJPH02.2 R68.1 RC106.2 U4.5 U4.6 U4.7 U4.8 UC1.AJ11 UC1.AL11 UC1.AL13
+0.95VALWP: PCH05.1 PCH06.1 PCH07.1 PCH08.1 PCH14.1 PCH17.1 PCH18.1 PCH19.1 PCH20.1 PJPH02.1 PLH01.2 PRH13.2
+0.95VS: C29.1 C30.1 CC98.1 CC99.1 J5.2 LC1.2 LC2.2 R56.1 RC103.2 U4.1 U4.2 U4.3
+0.95VS_APU_GFX: CC100.1 CC101.1 CC106.1 CC107.1 CC109.1 CC110.1 CC111.1 CC112.1 CC113.1 CC114.1 CC115.1 CC116.1 J5.1 LC1.1 LC2.1 RC1.1 UC1.AJ21 UC1.AJ23 UC1.AJ25 UC1.AJ27 UC1.AL23 UC1.AL25 UC1.AL27 UC1.AL29
+0.775VALW: C43.1 C45.1 PJP802.1 Q15.6 R64.1 R72.1
+1.2V_DDR: CC23.1 CC24.1 CC25.1 CC26.1 CC27.1 CC28.1 CC29.1 CC30.1 CC31.1 CC32.1 CC33.1 CC34.1 CC35.1 CC36.1 CC37.1 CC38.1 CC39.1 CC40.1 CC41.1 CC60.1 CC61.1 CC62.1 CC63.1 CC64.1 CD2.1 CD3.1 CD4.1 CD5.1 CD6.1 CD7.1 CD8.1 CD9.1 CD10.1 CD11.1 CD12.1 CD13.1 CD14.1 CD15.1 CD19.1 CD22.1 CD23.1 CD24.1 CD25.1 CD29.1 CD30.1 CD31.1 CD32.1 CD33.1 CD37.1 CD38.1 DC3.2 JDIMM1.111 JDIMM1.112 JDIMM1.117 JDIMM1.118 JDIMM1.123 JDIMM1.124 JDIMM1.129 JDIMM1.130 JDIMM1.135 JDIMM1.136 JDIMM1.141 JDIMM1.142 JDIMM1.147 JDIMM1.148 JDIMM1.153 JDIMM1.154 JDIMM1.159 JDIMM1.160 JDIMM1.163 PJPM02.2 RC4.2 RC5.2 RC6.1 RD1.1 RD2.2 UC1.AA35 UC1.AC32 UC1.AC37 UC1.AE32 UC1.AE35 UC1.AG32 UC1.AG37 UC1.AJ32 UC1.AJ35 UC1.AL32 UC1.AL37 UC1.AR35 UC1.J35 UC1.L32 UC1.L37 UC1.N35 UC1.R37 UC1.U32 UC1.U35 UC1.W32 UC1.W37
+1.2VP: PCM05.1 PCM06.1 PCM07.1 PCM08.1 PCM09.1 PCM10.1 PJPM02.1 PLM01.1 PRM14.2 PUM01.5 PUM01.19
+1.8V_ALW: C22.1 CC92.1 CC93.1 PJP801.1 PJP1802.2 QA2.1 RC96.1 RC117.1 RE7.1 U3.1 U3.2 UC1.AJ13 UC1.AL15
+1.8V_AVDD: CA495.1 RA35.2 UA1.33
+1.8V_CPVDD: CA46.1 CA50.1 CA484.1 CA492.1 RA36.2 UA1.29
+1.8V_DVDDIO: CA477.1 CA490.1 RA65.2 UA1.8
+1.8VALWP: PC1802.1 PC1803.1 PC1804.1 PC1807.1 PJP1802.1 PL1812.2 PR1806.1
+1.8VS: CC79.1 CC80.1 J3.2 JHDT1.1 JHDT1.19 PRZ23.1 Q1.2 Q1.5 QA2.3 QC1.2 QC2.2 QC2.5 R2.1 R3.1 RA35.1 RA36.1 RA65.1 RC11.1 RC14.1 RC16.1 RC17.1 RC18.1 RC24.2 RC25.2 RC26.1 RC33.1 RC114.2 RC118.1 RC123.1 RPC1.6 RPC1.7 RPC1.8 RPC7.1 RPC7.2 RPH1.5 RPH1.6 RPH1.7 RPH1.8 RPH2.7 UC1.AJ15 UC1.AL17 UC9.5 UC10.5
+1.8VS_LS: C23.1 J3.1 U3.13 U3.14
+2.5V_MEM: CD39.1 CD40.1 CD41.1 CD43.1 DD1.2 JDIMM1.257 JDIMM1.259 PJP2502.2
+2.5VP: PC2502.1 PC2505.1 PJP2502.1 PR2502.1 PU2501.6
+3V_DVDD: CA44.1 CA48.1 CA483.1 CA485.1 RA8.1 RA33.2 RA40.2 UA1.1
+3VALW: C31.1 C32.1 CC13.1 CL19.1 CW8.1 JP6.2 JPWR1.4 PC802.1 PJP302.2 PJP1801.1 PJP2501.1 PL1811.1 PR5.2 PR33.1 PR41.2 PR1803.1 PRB42.1 PRH03.1 PRH05.1 PRM06.1 PU800.5 PU800.6 PU800.7 PU800.8 R28.1 R57.2 R63.2 R78.1 RA41.2 RC22.1 RC42.1 RC44.1 RC48.1 RC55.2 RC59.2 RC68.1 RC69.1 RC70.1 RC71.1 RC72.1 RC73.1 RC74.1 RC79.1 RC80.1 RC81.1 RC82.1 RC132.2 RE3.2 RE17.2 RE18.2 RE19.1 RL10.1 RPC6.7 RPC6.8 U2.6 U2.7 UC1.AJ17 UC1.AL19 UC13.5 UL2.5 UW1.5
+3VALW_1.8V: PC1801.1 PJP1801.2 PL1811.2 PU1801.8 PU1801.9 PU1801.10
+3VALW_2.5V: PC2501.1 PJP2501.2 PU2501.3
+3VALW_EC: CE1.1 CE2.1 CE3.1 CE4.1 LE1.1 PR9.1 RE2.1 RE3.1 RE5.2 RE8.1 RE13.1 RE14.1 RE23.2 RE24.2 RE25.2 RE36.2 RE39.2 RE47.1 RE50.1 UC11.5 UC12.5 UE1.9 UE1.22 UE1.33 UE1.96 YE1.4
+3VALWP: PC310.1 PC311.1 PC312.1 PC313.1 PC314.1 PC316.1 PJP302.1 PL301.2 PR304.1 PR306.2 PR504.1 PU301.14
+3VLP: JP2.1 PC308.1 PC902.1 PD900.2 PR902.1 PU301.16 PU301.17 PU900.8 RE2.2 RE6.1 RE44.1
+3VS: C10.1 C11.1 C26.1 C27.1 CD42.1 CS1.1 CS2.1 CS18.1 CS19.1 CV1.1 CV10.1 CV11.1 CW1.1 CW2.1 CW3.1 F1.1 J4.1 JDIMM1.255 JIOB1.12 JP5.2 PRZ21.1 PRZ70.1 Q10.2 QA2.2 QV1.2 QV2.1 QV3.2 QV3.5 R1.1 R4.1 R7.2 R13.1 R17.1 R19.1 R27.1 R37.1 R45.1 R46.1 R47.1 R49.1 R50.1 RA33.1 RC8.2 RC19.2 RC20.2 RC34.2 RC35.2 RC36.2 RC53.1 RC56.2 RC57.2 RC76.1 RC77.1 RC78.1 RC98.1 RC99.1 RC101.1 RC104.1 RC113.1 RC122.1 RC130.2 RD6.2 RE10.1 RE15.1 RE21.1 RE51.2 RE52.2 RL8.1 RPC6.5 RPC6.6 RPC7.3 RS3.2 RS4.2 RS5.1 RS6.1 RS7.1 RS8.1 RS9.1 RS10.1 RS11.1 RS12.1 RS14.2 RS25.1 RV3.1 RV27.1 RV36.1 RV37.1 RW2.2 U1.1 US2.2 US2.3 US2.9 US2.10 UV1.5
+3VS_APU: CC78.1 RC122.2 UC1.AJ19 UC1.AL21
+3VS_CAM: C3.1 F1.2 JEDP1.29 R7.1
+3VS_SSD: CS23.1 CS24.1 CS25.1 CS26.1 CS27.1 CS28.1 CS29.1 CS30.1 JP5.1 JSSD1.2 JSSD1.4 JSSD1.14 JSSD1.16 JSSD1.18 JSSD1.70 JSSD1.72 JSSD1.74 RE49.2
+3VS_TOUCH: C4.2 JTP1.8 Q2.2 Q3.1 Q5.2 Q5.5 R21.2 R23.1 R25.1 R26.1 R27.2 R29.2 R32.2 R33.2 R35.2 RE26.2
+3VS_WLAN_NGFF: CW4.1 CW5.1 CW6.1 CW7.1 JWLAN1.2 JWLAN1.4 JWLAN1.72 JWLAN1.74 RW2.1 RW10.2 RW11.2 UW1.1
+5V_AVDD: CA45.1 CA49.1 CA475.1 CA481.1 RA34.1 UA1.20
+5V_HDD: CS11.1 CS12.1 CS13.1 JHDD1.10 JHDD1.11 JHDD1.12 JP3.2 RS24.1
+5V_HDMI: CV17.1 FV2.1 JHDMI1.18 RV38.1 RV39.1
+5V_PVDD: CA2.1 CA3.1 CA43.1 CA47.1 CA474.1 CA494.1 RA1.2 UA1.34 UA1.39
+5V_USB_PWR1: CU2.1 CU3.1 CU4.1 CU5.1 CU15.1 CU17.1 CU18.1 CU19.1 JUSB1.1 JUSB2.1 UU1.1
+5V_USB_PWR2: JIOB1.13 JIOB1.14 JIOB1.15 JIOB1.16 UU2.1
+5VALW: C33.1 C34.1 C48.1 CU7.1 CU8.1 CU22.1 CU23.1 PD2.3 PD3.3 PJP502.2 PR4.1 PR2504.1 PRH11.1 PRM04.1 PRM05.2 Q8.3 Q9.3 R54.2 R55.2 R58.1 R59.2 RE16.1 U2.1 U2.2 U2.4 U3.4 U5.8 U6.4 UU1.5 UU2.5
+5VALW_VDD: PC2504.1 PR2504.2 PU2501.4
+5VALWP: PC510.1 PC511.1 PC512.1 PC513.1 PC514.1 PC518.1 PC519.1 PC520.1 PJP502.1 PL501.2 PR509.2 PU501.14
+5VS: C5.1 C18.1 C19.1 C53.1 F3.1 FV2.2 J1.1 J2.1 JFAN1.1 JP3.1 JP4.1 PCZ55.1 PRZ26.2 PUZ01.12 PUZ01.26 Q11.3 R14.1 R36.1 R48.1 RA1.1 RA34.2 RE43.1
+5VS_KBL: C6.1 F3.2 JKBBL1.1
+5VS_ODD: CS20.1 CS21.1 CS22.1 JODD1.17 JODD1.18 JODD1.19 JODD1.20 JODD1.21 JODD1.22 JP4.2
+17.4V_BATT: PCB28.2 PD14.2 PLB01.2 PQB13.1 PQB13.2 PQB13.3 PRB01.1
+17.4V_BATT+: PC11.1 PCB30.1 PCB31.1 PCB32.1 PCB33.1 PCB34.1 PJP3.1 PL4.1 PQB28.3 PRB01.4 PRB35.1 PRB41.1
+17.4V_BATT++: PBATT1.8 PBATT1.9 PBATT1.10 PC12.1 PJP3.2 PL4.2
+19V_ADPIN: PC1.1 PC2.1 PC15.1 PJP1.1 PJPDC1.5 PJPDC1.6 PL1.1
+19V_VIN: PC3.1 PC4.1 PDB01.2 PJP1.2 PL1.2 PQB11.5 PR32.1 PR34.1 PR36.1 PRB09.1
+19VB: FV1.1 PD14.3 PD900.3 PDB13.2 PJP301.1 PJP501.1 PJPB01.1 PJPH01.1 PJPM01.1 PJPZ01.1 PL311.1 PL511.1 PLB02.1 PLH11.1 PLM11.1 PLZ01.2 PQB13.5 PR302.2 PR906.1 PRB02.4 RV9.1
+19VB_0.95V: PCH01.1 PCH02.1 PCH03.1 PCH04.1 PCH15.1 PCH16.1 PJPH01.2 PLH11.2 PUH01.5
+19VB_1.2V: PCM01.1 PCM02.1 PCM03.1 PCM04.1 PCM22.1 PCM23.1 PJPM01.2 PLM11.2 PQM01.2 PQM01.3 PQM01.4 PQM01.10 PRM07.1
+19VB_3V: PC301.1 PC302.1 PC303.1 PC304.1 PC305.1 PC306.1 PJP301.2 PL311.2 PU301.2 PU301.3 PU301.4 PU301.5
+19VB_5V: PC501.1 PC502.1 PC503.1 PC504.1 PC505.1 PC506.1 PJP501.2 PL511.2 PU501.2 PU501.3 PU501.4 PU501.5
+19VB_APU: PCZ00.1 PCZ02.1 PCZ03.1 PCZ39.1 PCZ56.1 PCZ67.1 PCZ69.1 PCZ70.1 PCZ71.1 PCZ72.1 PCZ73.1 PCZ74.1 PCZ75.1 PCZ76.1 PCZ90.1 PJPZ01.2 PLZ01.1 PQZ01.5 PQZ04.5
+19VB_CHG: PCB20.1 PCB21.1 PCB22.1 PCB23.1 PCB24.1 PCB25.1 PCB26.1 PCB27.1 PDB13.3 PJPB01.2 PLB02.2 PQB26.5
+VCC0: RE6.2 UE1.111
+VCC_IO2: RE7.2 RE8.2 UE1.124
+VDD_TOUCH: F2.2 JEDP1.40 R20.2
+VDDCR_FCH_ALW: C41.1 CC94.1 CC95.1 CC96.1 R61.2 R73.2 UC1.AR4 UC1.AR5 UC1.AR7 UC1.AU7
+VDDREG: CL12.1 RL4.2 UL1.23
GND: C1.2 C2.2 C3.2 C4.1 C5.2 C6.2 C7.2 C8.2 C10.2 C11.2 C14.2 C15.2 C16.1 C17.2 C18.2 C19.2 C20.1 C21.1 C22.2 C23.2 C24.2 C25.1 C26.2 C27.2 C28.2 C29.2 C30.2 C31.2 C32.2 C33.2 C34.2 C35.2 C36.2 C37.2 C38.2 C39.2 C40.2 C41.2 C42.2 C43.2 C44.2 C45.2 C46.2 C47.2 C48.2 C49.2 C53.2 CA2.2 CA3.2 CA25.2 CA27.2 CA28.2 CA43.2 CA44.2 CA45.2 CA46.2 CA47.2 CA48.2 CA49.2 CA50.2 CA51.2 CA52.2 CA53.2 CA474.2 CA476.2 CA477.2 CA480.2 CA483.2 CA484.2 CA485.2 CA486.2 CA487.1 CA490.2 CA491.2 CA492.2 CA493.1 CA494.2 CC3.2 CC4.2 CC5.1 CC6.1 CC7.2 CC8.2 CC9.2 CC10.2 CC11.2 CC12.2 CC13.2 CC14.1 CC15.1 CC16.2 CC18.2 CC19.2 CC21.2 CC22.1 CC23.2 CC24.2 CC25.2 CC26.2 CC27.2 CC28.2 CC29.2 CC30.2 CC31.2 CC32.2 CC33.2 CC34.2 CC35.2 CC36.2 CC37.2 CC38.2 CC39.2 CC40.2 CC41.2 CC42.2 CC48.2 CC51.2 CC52.2 CC53.2 CC54.2 CC55.2 CC56.2 CC57.2 CC58.2 CC59.2 CC60.2 CC61.2 CC62.2 CC63.2 CC64.2 CC65.2 CC66.2 CC67.2 CC68.2 CC69.2 CC70.2 CC71.2 CC72.2 CC73.2 CC74.2 CC75.2 CC76.2 CC77.2 CC78.2 CC79.2 CC80.2 CC85.2 CC86.2 CC87.2 CC88.2 CC89.2 CC92.2 CC93.2 CC94.2 CC95.2 CC96.2 CC97.1 CC98.2 CC99.2 CC100.2 CC101.2 CC102.2 CC103.2 CC104.2 CC105.2 CC106.2 CC107.2 CC109.2 CC110.2 CC111.2 CC112.2 CC113.2 CC114.2 CC115.2 CC116.2 CC119.2 CC120.2 CC121.2 CC122.2 CC123.2 CC124.2 CC125.2 CC126.2 CC127.2 CC129.2 CC130.2 CD1.2 CD2.2 CD3.2 CD4.2 CD5.2 CD6.2 CD7.2 CD8.2 CD9.2 CD10.2 CD11.2 CD12.2 CD13.2 CD14.2 CD15.2 CD16.2 CD17.2 CD18.2 CD19.2 CD20.2 CD21.2 CD22.2 CD23.2 CD24.2 CD25.2 CD26.2 CD27.2 CD28.2 CD29.2 CD30.2 CD31.2 CD32.2 CD33.2 CD34.2 CD35.2 CD36.2 CD37.2 CD38.2 CD39.2 CD40.2 CD41.2 CD42.2 CD43.2 CD44.2 CE1.2 CE2.2 CE3.2 CE4.2 CE8.2 CE9.2 CE10.1 CE11.2 CE12.2 CE13.2 CE14.2 CE15.2 CE16.2 CE17.2 CE18.2 CE19.2 CH1.2 CH2.2 CL1.2 CL2.2 CL3.2 CL4.2 CL5.2 CL6.2 CL7.2 CL10.2 CL11.2 CL12.2 CL15.2 CL16.2 CL17.2 CL18.2 CL19.2 CL20.2 CL21.2 CLRP1.2 CS1.2 CS2.2 CS11.2 CS12.2 CS13.2 CS18.2 CS19.2 CS20.2 CS21.2 CS22.2 CS23.2 CS24.2 CS25.2 CS26.2 CS27.2 CS28.2 CS29.2 CS30.2 CS35.2 CU1.1 CU2.2 CU3.2 CU4.2 CU5.2 CU7.2 CU8.2 CU12.2 CU13.2 CU15.2 CU17.2 CU18.2 CU19.2 CU22.2 CU23.2 CU24.2 CU25.2 CV1.2 CV8.2 CV9.2 CV10.2 CV11.2 CV12.2 CV13.2 CV14.2 CV17.2 CV24.2 CW1.2 CW2.2 CW3.2 CW4.2 CW5.2 CW6.2 CW7.2 CW8.2 D1.1 DA1.1 DA2.1 DA5.1 DA8.1 DA9.1 DC1.1 DC3.1 DD1.1 DD2.1 DE2.1 EC1.2 EC2.2 ED1.1 ED2.1 ED3.1 EL1.3 EU1.1 EU2.1 EU3.1 EU4.3 EU5.1 EU6.3 H1.1(TP-1) H2.1(TP-1) H4.1(TP-1) H5.1(TP-1) H6.1(TP-1) H7.1(TP-1) H8.1(TP-1) H12.1(TP-1) H13.1(TP-1) HCPU1.1(TP-1) HCPU2.1(TP-1) HCPU3.1(TP-1) HCPU4.1(TP-1) JDIMM1.1 JDIMM1.2 JDIMM1.5 JDIMM1.6 JDIMM1.9 JDIMM1.10 JDIMM1.14 JDIMM1.15 JDIMM1.18 JDIMM1.19 JDIMM1.22 JDIMM1.23 JDIMM1.26 JDIMM1.27 JDIMM1.30 JDIMM1.31 JDIMM1.35 JDIMM1.36 JDIMM1.39 JDIMM1.40 JDIMM1.43 JDIMM1.44 JDIMM1.47 JDIMM1.48 JDIMM1.51 JDIMM1.52 JDIMM1.56 JDIMM1.57 JDIMM1.60 JDIMM1.61 JDIMM1.64 JDIMM1.65 JDIMM1.68 JDIMM1.69 JDIMM1.72 JDIMM1.73 JDIMM1.77 JDIMM1.78 JDIMM1.81 JDIMM1.82 JDIMM1.85 JDIMM1.86 JDIMM1.89 JDIMM1.90 JDIMM1.93 JDIMM1.94 JDIMM1.98 JDIMM1.99 JDIMM1.102 JDIMM1.103 JDIMM1.106 JDIMM1.107 JDIMM1.166 JDIMM1.167 JDIMM1.168 JDIMM1.171 JDIMM1.172 JDIMM1.175 JDIMM1.176 JDIMM1.180 JDIMM1.181 JDIMM1.184 JDIMM1.185 JDIMM1.188 JDIMM1.189 JDIMM1.192 JDIMM1.193 JDIMM1.196 JDIMM1.197 JDIMM1.201 JDIMM1.202 JDIMM1.205 JDIMM1.206 JDIMM1.209 JDIMM1.210 JDIMM1.213 JDIMM1.214 JDIMM1.217 JDIMM1.218 JDIMM1.222 JDIMM1.223 JDIMM1.226 JDIMM1.227 JDIMM1.230 JDIMM1.231 JDIMM1.234 JDIMM1.235 JDIMM1.238 JDIMM1.239 JDIMM1.243 JDIMM1.244 JDIMM1.247 JDIMM1.248 JDIMM1.251 JDIMM1.252 JDIMM1.260 JDIMM1.261 JDIMM1.262 JEDP1.13 JEDP1.17 JEDP1.20 JEDP1.23 JEDP1.32 JEDP1.35 JEDP1.38 JEDP1.41 JEDP1.42 JFAN1.4 JFAN1.5 JFAN1.6 JFP1.1 JFP1.3 JFP1.4 JFP1.9 JFP1.10 JHDD1.1 JHDD1.4 JHDD1.7 JHDD1.13 JHDD1.14 JHDMI1.2 JHDMI1.5 JHDMI1.8 JHDMI1.11 JHDMI1.17 JHDMI1.20 JHDMI1.21 JHDMI1.22 JHDMI1.23 JHDT1.3 JHDT1.5 JHDT1.7 JHDT1.17 JIOB1.1 JIOB1.2 JIOB1.5 JIOB1.8 JIOB1.9 JIOB1.10 JIOB1.17 JIOB1.18 JKB1.31 JKB1.32 JKBBL1.5 JKBBL1.6 JLAN1.9 JLAN1.10 JLAN1.11 JLAN1.12 JODD1.1 JODD1.2 JODD1.7 JODD1.8 JODD1.13 JODD1.14 JODD1.25 JODD1.26 JPWR1.1 JPWR1.5 JPWR1.6 JRTC1.2 JSPK1.5 JSPK1.6 JSSD1.1 JSSD1.3 JSSD1.9 JSSD1.15 JSSD1.21 JSSD1.27 JSSD1.33 JSSD1.39 JSSD1.45 JSSD1.51 JSSD1.57 JSSD1.71 JSSD1.73 JSSD1.75 JSSD1.76 JSSD1.77 JTP1.5 JTP1.9 JTP1.10 JUSB1.4 JUSB1.7 JUSB1.10 JUSB1.11 JUSB1.12 JUSB1.13 JUSB2.4 JUSB2.7 JUSB2.10 JUSB2.11 JUSB2.12 JUSB2.13 JWLAN1.1 JWLAN1.7 JWLAN1.13 JWLAN1.18 JWLAN1.19 JWLAN1.33 JWLAN1.39 JWLAN1.45 JWLAN1.51 JWLAN1.57 JWLAN1.63 JWLAN1.69 JWLAN1.75 JWLAN1.76 JWLAN1.77 LE2.2 LED1.1 LED1.3 PBATT1.1 PBATT1.2 PBATT1.3 PBATT1.4 PBATT1.11 PBATT1.12 PC1.2 PC2.2 PC3.2 PC4.2 PC11.2 PC12.2 PC15.2 PC301.2 PC302.2 PC303.2 PC304.2 PC305.2 PC306.2 PC308.2 PC309.2 PC310.2 PC311.2 PC312.2 PC313.2 PC314.2 PC316.2 PC317.2 PC501.2 PC502.2 PC503.2 PC504.2 PC505.2 PC506.2 PC508.2 PC509.2 PC510.2 PC511.2 PC512.2 PC513.2 PC514.2 PC515.2 PC516.1 PC518.2 PC519.2 PC520.2 PC801.1 PC802.2 PC803.2 PC804.2 PC805.2 PC901.1 PC902.2 PC903.1 PC904.1 PC905.2 PC908.2 PC909.2 PC910.2 PC911.2 PC1801.2 PC1802.2 PC1803.2 PC1804.2 PC1805.2 PC1806.2 PC2501.2 PC2502.2 PC2503.2 PC2504.2 PCB02.2 PCB04.2 PCB05.2 PCB07.1 PCB08.1 PCB09.2 PCB10.2 PCB11.2 PCB12.2 PCB13.2 PCB14.2 PCB16.2 PCB17.2 PCB19.2 PCB20.2 PCB21.2 PCB22.2 PCB23.2 PCB24.2 PCB25.2 PCB26.2 PCB27.2 PCB29.2 PCB30.2 PCB31.2 PCB32.2 PCB33.2 PCB34.2 PCB36.2 PCB70.2 PCH01.2 PCH02.2 PCH03.2 PCH04.2 PCH05.2 PCH06.2 PCH07.2 PCH08.2 PCH09.2 PCH10.2 PCH11.2 PCH13.2 PCH15.2 PCH16.2 PCH17.2 PCH18.2 PCH19.2 PCH20.2 PCM01.2 PCM02.2 PCM03.2 PCM04.2 PCM05.2 PCM06.2 PCM07.2 PCM08.2 PCM09.2 PCM10.2 PCM11.2 PCM13.2 PCM14.2 PCM15.2 PCM16.2 PCM18.2 PCM19.2 PCM20.2 PCM22.2 PCM23.2 PCZ00.2 PCZ02.2 PCZ03.2 PCZ04.1 PCZ10.1 PCZ13.2 PCZ14.2 PCZ18.1 PCZ37.2 PCZ39.2 PCZ54.2 PCZ55.2 PCZ56.2 PCZ58.2 PCZ59.2 PCZ62.1 PCZ63.2 PCZ64.2 PCZ65.2 PCZ67.2 PCZ69.2 PCZ70.2 PCZ71.2 PCZ72.2 PCZ73.2 PCZ74.2 PCZ75.2 PCZ76.2 PCZ77.2 PCZ78.2 PCZ79.2 PCZ80.2 PCZ86.2 PCZ87.2 PCZ88.2 PCZ89.2 PCZ90.2 PCZ91.2 PCZ92.2 PCZ93.2 PCZ94.2 PCZ95.2 PCZ96.2 PCZ97.2 PCZ98.2 PCZ101.2 PCZ102.2 PCZ103.2 PCZ104.2 PD1.1 PD2.2 PD3.2 PD5.1 PD6.1 PD14.1 PDB13.1 PDM01.2 PHZ2.1 PHZ3.1 PJP2.2 PJPDC1.7 PJPDC1.8 PL2.2 PQ2.3 PQ11.3 PQ12.1 PQ12.4 PQ13.1 PQ13.4 PQ801.3 PQ900.1 PQ900.4 PQB25.1 PQB25.2 PQB25.3 PQB29.3 PQB31.3 PQB32.3 PQB33.3 PQM01.5 PQM01.6 PQM01.7 PQZ02.1 PQZ02.2 PQZ02.3 PQZ03.1 PQZ03.2 PQZ03.3 PQZ05.1 PQZ05.2 PQZ05.3 PQZ06.1 PQZ06.2 PQZ06.3 PR6.2 PR38.2 PR40.2 PR43.2 PR44.1 PR45.2 PR303.2 PR508.2 PR803.2 PR903.1 PR905.1 PR908.1 PR911.2 PR1802.2 PR1805.2 PR2503.2 PRB04.2 PRB10.2 PRB13.1 PRB16.2 PRB17.1 PRB23.2 PRB26.2 PRB28.1 PRB38.2 PRB45.2 PRH02.2 PRH04.2 PRH09.2 PRH15.1 PRM11.2 PRZ05.2 PRZ18.1 PRZ67.2 PRZ76.1 PRZ78.2 PRZ81.1 PRZ86.1 PRZ87.1 PU301.7 PU301.8 PU301.18 PU301.21 PU501.7 PU501.8 PU501.18 PU501.21 PU800.2 PU800.9 PU900.4 PU1801.11 PU2501.8 PU2501.9 PUB01.33 PUH01.4 PUH01.8 PUM01.1 PUM01.3 PUM01.14 PUM01.21 PUZ01.41 Q4.3 Q6.3 Q14.1 Q14.4 Q15.4 Q16.3 Q17.3 QC3.3 QE1.3 QS1.1 QS1.4 QV1.3 R21.1 R31.2 R41.2 R42.2 R60.1 RA32.1 RA38.2 RA39.2 RA48.2 RA63.2 RC2.2 RC7.1 RC13.2 RC15.2 RC27.2 RC28.2 RC41.1 RC43.1 RC45.1 RC49.1 RC60.1 RC61.1 RC65.1 RC75.1 RC83.1 RC84.1 RC85.1 RC86.1 RC87.1 RC88.2 RC89.2 RC90.2 RC91.2 RC92.2 RC94.2 RC95.2 RC100.2 RC102.2 RC105.2 RC108.1 RC112.1 RC115.2 RC126.2 RC133.1 RD3.1 RD4.1 RD5.1 RE9.1 RE28.2 RE29.2 RE38.2 RE41.1 RE54.2 RH2.1 RH3.1 RH4.1 RL7.1 RL9.2 RL11.1 RPC2.2 RPC2.3 RPC2.4 RPC3.1 RPC3.2 RPC3.3 RPC3.4 RPC5.1 RPC5.2 RPC5.3 RPC5.4 RPH2.5 RPH2.6 RS13.2 RS15.2 RS16.2 RS17.2 RS18.2 RS19.2 RS20.2 RS21.2 RV1.2 RV6.2 RV7.2 RV10.2 RV27.2 RV31.2 RV32.2 SW1.1 SW2.1 U1.5 U2.11 U2.15 U3.11 U3.15 U5.4 U6.9 UA1.41 UC1.A2 UC1.A8 UC1.A13 UC1.A18 UC1.A23 UC1.A32 UC1.A35 UC1.A39 UC1.AA1 UC1.AA2 UC1.AA3 UC1.AA5 UC1.AA10 UC1.AA39 UC1.AC3 UC1.AC7 UC1.AC10 UC1.AC11 UC1.AC13 UC1.AC15 UC1.AC17 UC1.AC19 UC1.AC21 UC1.AC23 UC1.AC25 UC1.AC27 UC1.AC29 UC1.AC31 UC1.AC38 UC1.AC39 UC1.AC41 UC1.AE3 UC1.AE5 UC1.AE10 UC1.AE39 UC1.AG3 UC1.AG7 UC1.AG10 UC1.AG11 UC1.AG13 UC1.AG15 UC1.AG17 UC1.AG19 UC1.AG21 UC1.AG23 UC1.AG25 UC1.AG27 UC1.AG29 UC1.AG31 UC1.AG39 UC1.AG41 UC1.AJ3 UC1.AJ5 UC1.AJ10 UC1.AJ29 UC1.AJ31 UC1.AJ39 UC1.AL1 UC1.AL2 UC1.AL3 UC1.AL7 UC1.AL10 UC1.AL31 UC1.AL39 UC1.AL41 UC1.AM25 UC1.AM27 UC1.AM29 UC1.AM31 UC1.AN3 UC1.AN5 UC1.AN39 UC1.AR3 UC1.AR11 UC1.AR19 UC1.AR23 UC1.AR27 UC1.AR31 UC1.AR39 UC1.AR41 UC1.AU3 UC1.AU9 UC1.AU21 UC1.AU25 UC1.AU29 UC1.AU39 UC1.AW3 UC1.AW5 UC1.AW7 UC1.AW9 UC1.AW11 UC1.AW13 UC1.AW15 UC1.AW17 UC1.AW19 UC1.AW21 UC1.AW23 UC1.AW25 UC1.AW27 UC1.AW29 UC1.AW31 UC1.AW33 UC1.AW35 UC1.AW37 UC1.AW39 UC1.AW41 UC1.AY1 UC1.AY11 UC1.B8 UC1.B13 UC1.B32 UC1.B39 UC1.BA7 UC1.BA11 UC1.BA15 UC1.BA19 UC1.BA23 UC1.BA31 UC1.BA35 UC1.BA39 UC1.C3 UC1.C5 UC1.C7 UC1.C9 UC1.C11 UC1.C13 UC1.C15 UC1.C17 UC1.C19 UC1.C21 UC1.C23 UC1.C25 UC1.C27 UC1.C29 UC1.C31 UC1.C33 UC1.C35 UC1.C37 UC1.C39 UC1.C41 UC1.E1 UC1.E2 UC1.E3 UC1.E21 UC1.E25 UC1.E29 UC1.E35 UC1.E38 UC1.E39 UC1.G1 UC1.G2 UC1.G3 UC1.G11 UC1.G13 UC1.G23 UC1.G27 UC1.G31 UC1.G35 UC1.G37 UC1.G39 UC1.G41 UC1.H23 UC1.J3 UC1.J8 UC1.J39 UC1.L3 UC1.L8 UC1.L13 UC1.L19 UC1.L21 UC1.L23 UC1.L25 UC1.L27 UC1.L29 UC1.L31 UC1.L39 UC1.L41 UC1.N1 UC1.N2 UC1.N3 UC1.N39 UC1.R3 UC1.R11 UC1.R13 UC1.R15 UC1.R17 UC1.R19 UC1.R21 UC1.R23 UC1.R25 UC1.R27 UC1.R29 UC1.R31 UC1.R39 UC1.R41 UC1.U1 UC1.U2 UC1.U3 UC1.U10 UC1.U39 UC1.W3 UC1.W10 UC1.W11 UC1.W13 UC1.W15 UC1.W17 UC1.W19 UC1.W21 UC1.W23 UC1.W25 UC1.W27 UC1.W29 UC1.W31 UC1.W39 UC1.W41 UC9.3 UC10.3 UC11.3 UC12.3 UC13.3 UC14.4 UC15.2 UE1.11 UE1.24 UE1.35 UE1.94 UE1.113 UL1.33 UL2.2 US1.3 US1.21 US2.5 US2.6 US2.7 US2.8 UU1.2 UU2.2 UV1.2 UW1.2 YE1.2 YL1.2 YL1.4
GNDA: CA26.2 CA51.1 CA52.1 CA53.1 CA475.2 CA479.1 CA481.2 CA482.1 CA488.2 CA489.2 CA495.2 CA497.2 CA498.2 CA499.2 CA501.2 CA502.2 CA504.2 CA505.2 CA506.2 JHP1.7 RA38.1 RA39.1 RA47.1 RA54.2 RA57.2 RA62.2 RA63.1 UA1.19 UA1.31
V3D3_STB: RA37.1 RA41.1 UA1.16
VBAT: PCB14.1 PRB35.2 PUB01.31
VDD_1.2V: PCM14.1 PRM03.2 PRM04.2 PUM01.11
VDD_CHG: PCB08.2 PRB18.2 PRB25.1 PRB27.1 PRB39.2 PRB44.1 PUB01.18
VDDCR_FCH_S5: PC804.1 PJP802.2 PU800.4
VDDIO_APU: PCZ64.1 PRZ23.2 PUZ01.6
VDDIO_AUDIO: RC123.2 UC1.AM13
VDDP_1.2V: PCM13.1 PDM01.1 PRM05.1 PUM01.12
VDDP_CHG: PCB19.1 PRB39.1 PUB01.8
VIN_0.775V: PC801.2 PJP801.2 PR802.1 PU800.1
0.95_1.8VALW_PWREN: PR1801.1 PRH01.1 R66.2 UE1.127
0.775PW_EN#: PR801.1 RE47.2 UE1.17
0.775PW_EN_R: PC805.1 PQ801.2 PR801.2
32K_X1: CC18.1 RC97.2 UC1.BA2 YC1.1
32K_X2: CC19.1 RC97.1 UC1.AY2 YC1.2
48M_X1: C2.1 RC116.2 UC1.F2 YC2.1
48M_X2: C1.1 RC116.1 UC1.F1 YC2.3
+0.775MOS: Q15.1 R60.2 U5.2 U5.5
+APU_CORE: CC42.1 CC48.1 CC51.1 CC52.1 CC53.1 CC54.1 CC55.1 CC56.1 CC57.1 CC58.1 CC59.1 PCZ77.1 PCZ78.1 PCZ79.1 PCZ80.1 PCZ91.1 PCZ92.1 PCZ93.1 PCZ94.1 PCZ95.1 PCZ96.1 PCZ97.1 PCZ98.1 PLZ04.4 PR904.1 PRZ51.2 UC1.AA25 UC1.AA27 UC1.AA29 UC1.AA31 UC1.K21 UC1.K23 UC1.K25 UC1.K27 UC1.K29 UC1.K31 UC1.N21 UC1.N23 UC1.N25 UC1.N27 UC1.N29 UC1.N31 UC1.U23 UC1.U25 UC1.U27 UC1.U29 UC1.U31
+APU_CORE_NB: C36.1 C42.1 CC65.1 CC66.1 CC67.1 CC68.1 CC69.1 CC70.1 CC71.1 CC72.1 CC73.1 CC74.1 CC75.1 CC76.1 CC77.1 CC85.1 CC86.1 CC87.1 CC88.1 CC89.1 CC122.1 CC123.1 CC124.1 CC125.1 CC126.1 CC127.1 CC129.1 PCZ86.1 PCZ87.1 PCZ88.1 PCZ89.1 PCZ101.1 PCZ102.1 PCZ103.1 PCZ104.1 PLZ02.4 PRZ02.1 R71.1 U5.3 U6.1 U6.2 UC1.AA11 UC1.AA13 UC1.AA15 UC1.AA17 UC1.AA19 UC1.AA21 UC1.AA23 UC1.AE11 UC1.AE13 UC1.AE15 UC1.AE17 UC1.AE19 UC1.AE21 UC1.AE23 UC1.AE25 UC1.AE27 UC1.AE29 UC1.AE31 UC1.E9 UC1.E11 UC1.E13 UC1.E15 UC1.E17 UC1.E19 UC1.G7 UC1.J7 UC1.K11 UC1.K13 UC1.K15 UC1.K17 UC1.K19 UC1.L7 UC1.L10 UC1.L15 UC1.L17 UC1.N7 UC1.N11 UC1.N13 UC1.N15 UC1.N17 UC1.N19 UC1.R7 UC1.U7 UC1.U11 UC1.U13 UC1.U15 UC1.U17 UC1.U19 UC1.U21 UC1.W7
+CHGRTC: DC4.2 JP2.2
+EC_VCCA: CE5.1 LE1.2 UE1.67
+FP_VCC: CU1.2 JFP1.7 JFP1.8 R47.2 R48.2
+INV_PWR_SRC: CV8.1 CV9.1 FV1.2 JEDP1.1 JEDP1.2 JEDP1.3 RV9.2
+LAN_VDD10: CL3.1 CL4.1 CL5.1 CL6.1 CL16.1 CL18.1 RL1.2 UL1.3 UL1.8 UL1.22 UL1.30
+LAN_VDD33: CL10.1 CL11.1 CL15.1 CL17.1 JP6.1 RC131.1 RL4.1 RL6.1 UL1.11 UL1.32 UL2.1
+LCDVDD: LV1.1 UV1.1
+LCDVDD_CONN: CV12.1 CV13.1 CV14.1 JEDP1.7 JEDP1.8 LV1.2
+LINE1_VREFO_L: DA10.1 UA1.24
+MEM_VREF: CC3.1 CC4.1 RC3.1 RC5.1 RC7.2
+MIC2-VREFO: RA56.1 RA60.1 UA1.23
+RTC_APU: CC119.1 RC124.2 UC15.3
+RTC_APU_R: CC97.2 CC104.1 CC105.1 CLRP1.1 QE1.1 RC124.1 UC1.AM11
+RTCBATT: CC130.1 JIOB1.11 JRTC1.1 RC125.2
+RTCBATT_R: DC4.3 QC3.2 RC125.1 RC126.1
+RTCVCC: CC120.1 DC4.1 RA37.2 UC15.1
+SPI_VCC: CC22.2 RC117.2 RC118.2 RC119.2 RC120.2 RC121.2 UC14.8
+VREF_CA: CD20.1 CD21.1 CD28.1 CD36.1 JDIMM1.164 RD2.1 RD3.2
A_MIC_CLK: CA486.1 ED1.3 JEDP1.31 L5.1
A_MIC_DATA: CA491.1 ED1.2 JEDP1.30 RA46.1
AC_OFF#: PQB31.2 PRB45.1 UE1.27
ACAV_IN: CE10.2 RE37.1 UE1.110
ACIN_CHG: PCB02.1 PQB31.1 PR901.2 PRB09.2 PRB10.1 PUB01.16
ACLIN: PRB16.1 PRB18.1 PUB01.20
ACOK_CHG: PRB22.1 PUB01.24
AD_BID0: RE5.1 RE9.2 UE1.66
ADJ_2.5V: PC2505.2 PR2502.2 PR2503.1 PU2501.7
ADP_I: PCB13.1 PRB31.1 UE1.65
AGPIO8: RC42.2 RC52.1 UC1.AJ4
AGPIO11: RC82.2 RC95.1 UC1.AJ8
AGPIO25: RC37.1 UC1.AY13
ALERT#: R45.2 U1.6
APU_ALERT#: RPC1.3 UC1.A30
APU_DBRDY: JHDT1.14 UC1.A26
APU_DBREQ#: RH5.2 RPH1.4 UC1.A25
APU_DBREQ#_R: JHDT1.16 RH5.1
APU_DP1_CTRL_CLK: QV3.1 RV36.2 UC1.G17
APU_DP1_CTRL_DATA: QV3.4 RV37.2 UC1.H17
APU_DP1_HPD: QV2.3 RV32.1 UC1.D17
APU_DP1_N0: CV22.1 UC1.B14
APU_DP1_N1: CV20.1 UC1.B15
APU_DP1_N2: CV18.1 UC1.B16
APU_DP1_N3: CV15.1 UC1.B17
APU_DP1_P0: CV23.1 UC1.A14
APU_DP1_P1: CV21.1 UC1.A15
APU_DP1_P2: CV19.1 UC1.A16
APU_DP1_P3: CV16.1 UC1.A17
APU_FCH_POK: RC40.2 UE1.32
APU_FCH_PWRGD: CC7.1 CC11.1 CC12.1 RC38.2 RC40.1 RC54.1 UC12.2
APU_FCH_PWRGD_R: RC48.2 RC49.2 RC54.2 UC1.AE2 UC12.4
APU_ID: RC55.1 RC60.2 UC1.AL5
APU_PCIE_RST#: JSSD1.50 RC66.1 RC67.2 RL17.2 RW4.2 UC13.4
APU_PCIE_RST#_C: RC63.1 UC1.AE4
APU_PCIE_WAKE#: JSSD1.54 RC39.1 RC131.2 RE32.2 UL1.21
APU_PCIE_WAKE#_R: RC39.2 UC1.AE7
APU_PWRGD: CC6.2 DH1.2 PUZ01.9 RC17.2 RC51.2 RC127.1 UC1.G25
APU_PWRGD_BUF: DH1.1 JHDT1.10
APU_PWRGD_EC: RC127.2 UE1.108
APU_PWRGD_R: CC8.1 RC51.1 UC1.AJ2
APU_RST#: CC5.2 DH2.2 RC18.2 RC26.2 RC32.1 RC50.2 UC1.D29 UC11.4
APU_RST#_BUF: DH2.1 JHDT1.12
APU_RST#_EC: RC32.2 UC11.2 UE1.73
APU_RST#_R: CC9.1 RC50.1 UC1.AL4
APU_SCLK0: JDIMM1.253 RPC6.3 UC1.AY33 US2.1
APU_SDATA0: JDIMM1.254 RPC6.4 UC1.BA32 US2.4
APU_SIC: QC2.4 RPC1.1 UC1.B30
APU_SID: QC2.1 RPC1.2 UC1.B29
APU_SPI_CLK: RC110.1 RC128.2 UC14.6
APU_SPI_CLK_R: RC110.2 UC1.AY17
APU_SPI_CS1#: RC121.1 UC1.AY21 UC14.1
APU_SPI_CS1#_R: RC114.1 UC1.AY19
APU_SPI_HOLD#: RC119.1 UC1.BA18 UC14.7
APU_SPI_MISO: UC1.BA17 UC14.2
APU_SPI_MOSI: UC1.AY20 UC14.5
APU_SPI_TPMCS#: RC115.1 UC1.BA21
APU_SPI_WP#: RC120.1 UC1.BA20 UC14.3
APU_SPKR: CC10.1 DA7.2 UC1.AP29
APU_SVC: PUZ01.3 RC10.1 RC14.2
APU_SVC_R: RC10.2 UC1.E27
APU_SVD: PUZ01.5 RC12.1 RC16.2
APU_SVD_R: RC12.2 UC1.D27
APU_SVT: PUZ01.7 RC9.1 RC11.2
APU_SVT_R: RC9.2 UC1.H27
APU_TCK: JHDT1.2 RPH1.1 UC1.B27
APU_TDI: JHDT1.6 RPH1.3 UC1.B25
APU_TDO: JHDT1.8 UC1.A27
APU_TEST0: RC41.2 RC72.2 UC1.AF2
APU_TEST1: RC43.2 RC71.2 UC1.AE1
APU_TEST2: RC45.2 RC73.2 UC1.AC8
APU_TEST4: T2.1(TP-1) UC1.H29
APU_TEST5: T3.1(TP-1) UC1.G29
APU_TEST6: T4.1(TP-1) UC1.H25
APU_TEST9: T5.1(TP-1) UC1.R32
APU_TEST10: T6.1(TP-1) UC1.N32
APU_TEST14: RPC3.7 UC1.G21
APU_TEST15: RPC3.8 UC1.H21
APU_TEST16: RPC3.6 UC1.D23
APU_TEST17: RPC3.5 UC1.E23
APU_TEST18: JHDT1.20 RPH2.4 UC1.A28
APU_TEST19: JHDT1.18 RPH2.3 UC1.B28
APU_TEST28_H: T7.1(TP-1) UC1.N8
APU_TEST28_L: T8.1(TP-1) UC1.N10
APU_TEST31: T9.1(TP-1) UC1.H31
APU_TEST36: RC24.1 RC28.1 UC1.D25
APU_TEST41: RC25.1 RC27.1 UC1.B31
APU_TMS: JHDT1.4 RPH1.2 UC1.B26
APU_TRST#: CH2.1 RH1.1 RPH2.2 UC1.A29
APU_TRST#_R: CH1.1 JHDT1.9 RH1.2
APU_VDD_RUN_FB_L: PRZ67.1 PRZ69.2 RC29.2
APU_VDD_SEN: PRZ51.1 PRZ75.2 T10.1(TP-1) UC1.D31
APU_VDDIO_MEM_S3_FB_H: PRM13.2 T30.1(TP-1) UC1.D35
APU_VDDNB_SEN: PRZ02.2 PRZ06.1 T11.1(TP-1) UC1.E33
APU_VDDP_RUN_FB_H: PQH01.3 T31.1(TP-1) UC1.AM21
APU_VDDP_RUN_FB_L: PRH15.2 RC31.2
APU_VSS_SENSE_A: RC29.1 RC30.1 UC1.D33
APU_VSS_SENSE_B: RC31.1 UC1.AM23
ASGATE: PRB07.2 PUB01.7
AUD_HP1_JACK_L: CA505.1 RA58.1 RA59.2 UA1.25
AUD_HP1_JACK_L1: LA2.1 RA52.2 RA58.2
AUD_HP1_JACK_R: CA506.1 RA55.2 RA61.1 UA1.26
AUD_HP1_JACK_R1: LA3.1 RA53.2 RA61.2
AUD_PC_BEEP: CA478.2 UA1.11
AUD_PC_BEEP_C: DA7.1 RA31.1
AUD_SENSE_A: CA488.1 RA40.1 RA51.2 UA1.12
AUD_SPK_L+: LA17.1 UA1.35
AUD_SPK_L+_C: CA28.1 DA1.2 JSPK1.3 LA17.2
AUD_SPK_L-: LA18.1 UA1.36
AUD_SPK_L-_C: CA27.1 DA1.3 JSPK1.4 LA18.2
AUD_SPK_R+: LA15.1 UA1.38
AUD_SPK_R+_C: CA476.1 DA2.2 JSPK1.1 LA15.2
AUD_SPK_R-: LA16.1 UA1.37
AUD_SPK_R-_C: CA480.1 DA2.3 JSPK1.2 LA16.2
AUD_VREF: CA489.1 UA1.22
BA: PDB01.3 PQB28.1 PRB41.2
BATGONE: PCB09.1 PRB23.1 PRB24.1 PUB01.25
BATT_CHG_LED: Q9.1 R40.2
BATT_CHG_LED#: Q7.4 UE1.21
BATT_CHG_LED_R#: Q7.3 Q9.2 Q12.1
BATT_I: PCB10.1 PRB29.1 UE1.75
BATT_LOW_LED: Q8.1 R43.2
BATT_LOW_LED#: Q7.1 UE1.93
BATT_LOW_LED_R#: Q7.6 Q8.2
BEEP#: DA7.3 UE1.23
BGATE: PCB28.1 PQB13.4 PUB01.32
BKOFF#: DV1.2 RV33.2 UE1.105
BMON: PRB29.2 PUB01.27
BST1_APU: PRZ82.1 PUZ01.21
BST1_APU_R: PCZ38.1 PRZ82.2
BST_0.95V: PRH06.1 PUH01.1
BST_0.95V_R: PCH12.1 PRH06.2
BST_1.2V: PRM02.1 PUM01.18
BST_1.2V_R: PCM12.1 PRM02.2
